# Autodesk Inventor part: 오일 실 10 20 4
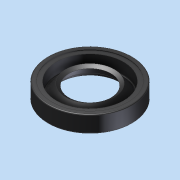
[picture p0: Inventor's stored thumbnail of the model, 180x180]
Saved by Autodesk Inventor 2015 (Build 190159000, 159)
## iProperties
Created: 2024-05
Part Number: 오일 실 10 20 4
Material: 일반
Document SubType Name: Modeling
Designer: Administrator
Density: 1 g/cm^3
Appearance: 기본값
Author: Administrator
Author: jhkim
Description: 오일 실 - 비스프링, 조립 GA
Creation Date: 2024-05-07
Sending System: Autodesk Inventor 2025
Preprocessor: ST-DEVELOPER v20
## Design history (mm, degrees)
node "오일 실 10 20 41"
body "Solid1"
node "기준1"
